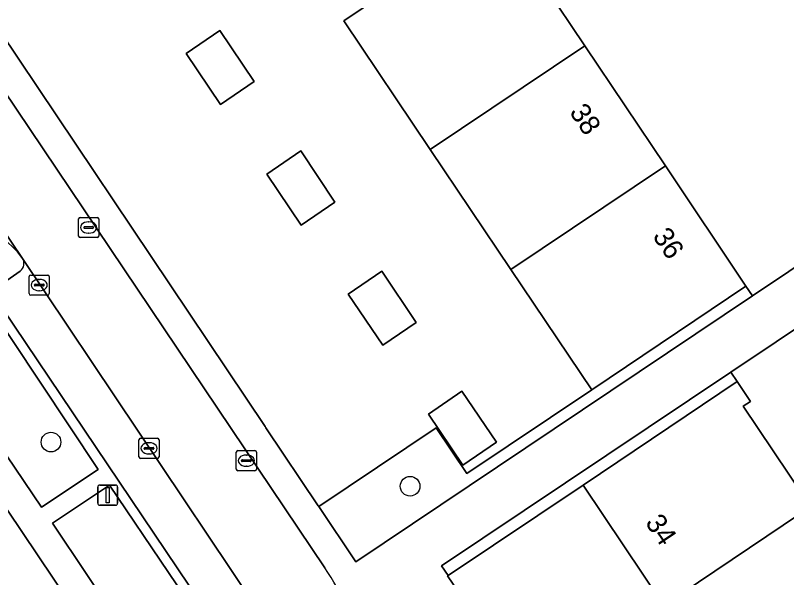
# Model space of a CAD drawing. Extents: x 158793 to 159888, y 384317 to 385256.
# Drawn here: x 159132.82 to 159171.17, y 384834.32 to 384862.27 of the extents above; entities that cross this region are included whole.
import ezdxf

# ---------------------------------------------------------------- set-up
doc = ezdxf.new("R2010")
doc.units = 0
for name, color, linetype in [('IMGEO_Boom', 7, 'Continuous'), ('IMGEO_Erf', 7, 'Continuous'), ('IMGEO_Groenvoorziening', 7, 'Continuous'), ('IMGEO_Kolk', 7, 'Continuous'), ('IMGEO_Lichtmast', 7, 'Continuous'), ('IMGEO_Pand', 7, 'Continuous'), ('IMGEO_Pand_nummerreeks', 7, 'Continuous'), ('IMGEO_Parkeervlak_open', 7, 'Continuous'), ('IMGEO_Rijbaan_lokaal_open', 7, 'Continuous'), ('IMGEO_Voetpad_open', 7, 'Continuous')]:
    doc.layers.add(name, color=color, linetype=linetype)

msp = doc.modelspace()

# ---------------------------------------------------------------- linework, layer by layer
at = {"layer": 'IMGEO_Boom'}
for centre in [(159134.592, 384841.055), (159152.449, 384838.86)]:
    msp.add_circle(centre, 0.489, dxfattribs=at)
at = {"layer": 'IMGEO_Erf'}
for points in [[(159129.189, 384865.748), (159145.236, 384841.838), (159145.281, 384841.77), (159147.886, 384837.889), (159147.91, 384837.853), (159153.744, 384841.768), (159155.277, 384839.485), (159161.48, 384843.659), (159157.462, 384849.64), (159153.451, 384855.61), (159149.155, 384862.006), (159151.132, 384863.344), (159147.414, 384868.879), (159143.399, 384874.856), (159138.645, 384881.934), (159140.628, 384883.267), (159137.261, 384888.273), (159133.15, 384894.387), (159129.299, 384900.113)], [(159178.672, 384807.366), (159174.655, 384813.355), (159170.638, 384819.344), (159173.118, 384820.976), (159169.097, 384826.953), (159165.075, 384832.93), (159161.054, 384838.907), (159154.343, 384834.428), (159154.314, 384834.409), (159155.612, 384832.486), (159157.414, 384829.817), (159158.347, 384828.435), (159166.834, 384815.86), (159164.988, 384814.597), (159177.008, 384796.687)]]:
    msp.add_lwpolyline(points, dxfattribs=at)
for points in [[(159142.985, 384861.523), (159144.7, 384858.986), (159143.015, 384857.836), (159141.307, 384860.374)], [(159148.707, 384852.981), (159147.034, 384851.839), (159145.325, 384854.381), (159147.013, 384855.54)], [(159151.039, 384849.551), (159152.759, 384847.01), (159151.088, 384845.867), (159149.37, 384848.405)], [(159155.029, 384843.585), (159156.752, 384841.043), (159155.08, 384839.91), (159153.361, 384842.448)]]:
    msp.add_lwpolyline(points, close=True, dxfattribs=at)
at = {"layer": 'IMGEO_Groenvoorziening'}
for points in [[(159157.136, 384866.739), (159161.141, 384860.764), (159165.145, 384854.79), (159169.15, 384848.815), (159169.48, 384848.323), (159178.617, 384854.449), (159173.187, 384865.839)], [(159179.731, 384852.112), (159168.401, 384844.531), (159168.717, 384844.067), (159169.38, 384843.079), (159169.012, 384842.838), (159172.028, 384838.344)], [(159127.59, 384851.332), (159126.404, 384850.498), (159125.828, 384850.069), (159134.112, 384837.817), (159136.939, 384839.685), (159131.178, 384848.335), (159131.464, 384848.516), (159131.607, 384848.549)], [(159131.607, 384848.549), (159133.059, 384849.561)]]:
    msp.add_lwpolyline(points, dxfattribs=at)
for points in [[(159169.48, 384848.323), (159169.15, 384848.815), (159161.48, 384843.659), (159155.277, 384839.485), (159153.744, 384841.768), (159147.91, 384837.853), (159149.746, 384835.092)], [(159161.054, 384838.907), (159168.717, 384844.067), (159168.401, 384844.531), (159154.011, 384834.902), (159154.343, 384834.428)], [(159137.509, 384838.918), (159134.663, 384837.03), (159139.797, 384829.364), (159140.593, 384828.294), (159143.37, 384830.219)]]:
    msp.add_lwpolyline(points, close=True, dxfattribs=at)
for centre, radius, start, end in [((159129.775, 384847.773), 4.176, 35.4147, 121.5438), ((159132.773, 384849.942), 0.476, 306.8491, 31.824)]:
    msp.add_arc(centre, radius, start, end, dxfattribs=at)
at = {"layer": 'IMGEO_Kolk'}
for p, q in [((159135.963, 384851.301), (159135.963, 384852.153)), ((159136.038, 384852.227), (159136.89, 384852.227)), ((159136.964, 384852.153), (159136.964, 384851.301)), ((159136.222, 384851.721), (159136.222, 384851.733)), ((159136.265, 384851.77), (159136.663, 384851.77)), ((159136.451, 384852.007), (159136.476, 384852.007)), ((159136.706, 384851.733), (159136.706, 384851.721)), ((159136.66, 384851.684), (159136.262, 384851.684)), ((159136.474, 384851.447), (159136.449, 384851.447)), ((159136.89, 384851.227), (159136.038, 384851.227)), ((159133.506, 384848.437), (159133.506, 384849.289)), ((159133.581, 384849.363), (159134.433, 384849.363)), ((159133.994, 384849.143), (159134.019, 384849.143)), ((159134.507, 384849.289), (159134.507, 384848.437)), ((159133.765, 384848.857), (159133.765, 384848.869)), ((159134.203, 384848.82), (159133.805, 384848.82)), ((159133.808, 384848.906), (159134.206, 384848.906)), ((159134.249, 384848.869), (159134.249, 384848.857)), ((159134.433, 384848.363), (159133.581, 384848.363)), ((159134.017, 384848.583), (159133.992, 384848.583)), ((159138.967, 384840.317), (159138.967, 384841.169)), ((159139.042, 384841.243), (159139.894, 384841.243)), ((159139.455, 384841.023), (159139.48, 384841.023)), ((159139.968, 384841.169), (159139.968, 384840.317)), ((159139.226, 384840.737), (159139.226, 384840.749)), ((159139.664, 384840.7), (159139.266, 384840.7)), ((159139.269, 384840.786), (159139.667, 384840.786)), ((159139.71, 384840.749), (159139.71, 384840.737)), ((159143.883, 384840.631), (159144.735, 384840.631)), ((159139.894, 384840.243), (159139.042, 384840.243)), ((159139.478, 384840.463), (159139.453, 384840.463)), ((159143.808, 384839.705), (159143.808, 384840.557)), ((159144.296, 384840.411), (159144.321, 384840.411)), ((159144.809, 384840.557), (159144.809, 384839.705)), ((159144.067, 384840.125), (159144.067, 384840.137)), ((159144.505, 384840.088), (159144.107, 384840.088)), ((159144.11, 384840.174), (159144.508, 384840.174)), ((159144.319, 384839.851), (159144.294, 384839.851)), ((159144.551, 384840.137), (159144.551, 384840.125)), ((159144.735, 384839.631), (159143.883, 384839.631))]:
    msp.add_line(p, q, dxfattribs=at)
for points in [[(159135.963, 384851.301), (159135.963, 384852.153)], [(159136.038, 384852.227), (159136.89, 384852.227)], [(159136.964, 384852.153), (159136.964, 384851.301)], [(159136.89, 384851.227), (159136.038, 384851.227)], [(159133.506, 384848.437), (159133.506, 384849.289)], [(159133.581, 384849.363), (159134.433, 384849.363)], [(159134.507, 384849.289), (159134.507, 384848.437)], [(159134.433, 384848.363), (159133.581, 384848.363)], [(159138.967, 384840.317), (159138.967, 384841.169)], [(159139.042, 384841.243), (159139.894, 384841.243)], [(159139.968, 384841.169), (159139.968, 384840.317)], [(159143.883, 384840.631), (159144.735, 384840.631)], [(159139.894, 384840.243), (159139.042, 384840.243)], [(159143.808, 384839.705), (159143.808, 384840.557)], [(159144.809, 384840.557), (159144.809, 384839.705)], [(159144.735, 384839.631), (159143.883, 384839.631)]]:
    msp.add_lwpolyline(points, dxfattribs=at)
for centre, radius, start, end in [((159136.04, 384852.151), 0.0765, 91.552, 178.448), ((159136.04, 384852.151), 0.0765, 91.552, 178.448), ((159136.888, 384852.151), 0.0765, 1.552, 88.448), ((159136.888, 384852.151), 0.0765, 1.552, 88.448), ((159136.262, 384851.73), 0.0403, 85.8775, 175.7526), ((159136.259, 384851.72), 0.0366, 178.938, 274.7102), ((159136.663, 384851.727), 0.043, 264.8664, 352.4533), ((159136.667, 384851.732), 0.0386, 1.7309, 96.639), ((159136.04, 384851.303), 0.0765, 181.552, 268.448), ((159136.04, 384851.303), 0.0765, 181.552, 268.448), ((159136.888, 384851.303), 0.0765, 271.552, 358.448), ((159136.888, 384851.303), 0.0765, 271.552, 358.448), ((159133.583, 384849.287), 0.0765, 91.552, 178.448), ((159133.583, 384849.287), 0.0765, 91.552, 178.448), ((159134.431, 384849.287), 0.0765, 1.552, 88.448), ((159134.431, 384849.287), 0.0765, 1.552, 88.448), ((159133.805, 384848.866), 0.0403, 85.8775, 175.7526), ((159133.802, 384848.856), 0.0366, 178.938, 274.7102), ((159134.206, 384848.863), 0.043, 264.8664, 352.4533), ((159134.21, 384848.868), 0.0386, 1.7309, 96.639), ((159133.583, 384848.439), 0.0765, 181.552, 268.448), ((159133.583, 384848.439), 0.0765, 181.552, 268.448), ((159134.431, 384848.439), 0.0765, 271.552, 358.448), ((159134.431, 384848.439), 0.0765, 271.552, 358.448), ((159139.044, 384841.167), 0.0765, 91.552, 178.448), ((159139.044, 384841.167), 0.0765, 91.552, 178.448), ((159139.892, 384841.167), 0.0765, 1.552, 88.448), ((159139.892, 384841.167), 0.0765, 1.552, 88.448), ((159139.266, 384840.746), 0.0403, 85.8775, 175.7526), ((159139.263, 384840.736), 0.0366, 178.938, 274.7102), ((159139.667, 384840.743), 0.043, 264.8664, 352.4533), ((159139.671, 384840.748), 0.0386, 1.7309, 96.639), ((159143.885, 384840.555), 0.0765, 91.552, 178.448), ((159143.885, 384840.555), 0.0765, 91.552, 178.448), ((159144.733, 384840.555), 0.0765, 1.552, 88.448), ((159144.733, 384840.555), 0.0765, 1.552, 88.448), ((159139.044, 384840.319), 0.0765, 181.552, 268.448), ((159139.044, 384840.319), 0.0765, 181.552, 268.448), ((159139.892, 384840.319), 0.0765, 271.552, 358.448), ((159139.892, 384840.319), 0.0765, 271.552, 358.448), ((159144.107, 384840.134), 0.0403, 85.8775, 175.7526), ((159144.104, 384840.124), 0.0366, 178.938, 274.7102), ((159144.508, 384840.131), 0.043, 264.8664, 352.4533), ((159144.512, 384840.136), 0.0386, 1.7309, 96.639), ((159143.885, 384839.707), 0.0765, 181.552, 268.448), ((159143.885, 384839.707), 0.0765, 181.552, 268.448), ((159144.733, 384839.707), 0.0765, 271.552, 358.448), ((159144.733, 384839.707), 0.0765, 271.552, 358.448)]:
    msp.add_arc(centre, radius, start, end, dxfattribs=at)
for centre, major_axis, ratio, start_param, end_param in [((159136.45, 384851.727), (-0.387, 0.002), 0.722429, 4.712389, 7.853982), ((159136.475, 384851.727), (-0.39, 0.002), 0.717154, 1.570796, 4.712389), ((159133.993, 384848.863), (-0.387, 0.002), 0.722429, 4.712389, 7.853982), ((159134.018, 384848.863), (-0.39, 0.002), 0.717154, 1.570796, 4.712389), ((159139.454, 384840.743), (-0.387, 0.002), 0.722429, 4.712389, 7.853982), ((159139.479, 384840.743), (-0.39, 0.002), 0.717154, 1.570796, 4.712389), ((159144.295, 384840.131), (-0.387, 0.002), 0.722429, 4.712389, 7.853982), ((159144.32, 384840.131), (-0.39, 0.002), 0.717154, 1.570796, 4.712389)]:
    msp.add_ellipse(centre, major_axis=major_axis, ratio=ratio, start_param=start_param, end_param=end_param, dxfattribs=at)
at = {"layer": 'IMGEO_Lichtmast'}
for p, q in [((159136.916, 384838.016), (159136.916, 384838.816)), ((159136.916, 384838.816), (159136.916, 384838.016)), ((159137.016, 384838.916), (159137.806, 384838.916)), ((159137.806, 384838.916), (159137.016, 384838.916)), ((159137.906, 384838.816), (159137.906, 384838.016)), ((159137.906, 384838.016), (159137.906, 384838.816)), ((159137.806, 384837.916), (159137.016, 384837.916)), ((159137.016, 384837.916), (159137.806, 384837.916))]:
    msp.add_line(p, q, dxfattribs=at)
msp.add_lwpolyline([(159137.336, 384838.791), (159137.486, 384838.791), (159137.486, 384838.041), (159137.336, 384838.041), (159137.336, 384838.791)], dxfattribs=at)
for centre, start, end in [((159137.016, 384838.816), 90, 180), ((159137.016, 384838.816), 90, 180), ((159137.806, 384838.816), 0, 90), ((159137.806, 384838.816), 360, 90), ((159137.016, 384838.016), 180, 270), ((159137.016, 384838.016), 180, 270), ((159137.806, 384838.016), 270, 0), ((159137.806, 384838.016), 270, 0)]:
    msp.add_arc(centre, 0.1, start, end, dxfattribs=at)
at = {"layer": 'IMGEO_Pand'}
for points in [[(159157.136, 384866.739), (159151.409, 384862.932), (159151.132, 384863.344), (159149.155, 384862.006), (159153.451, 384855.61), (159161.141, 384860.764)], [(159143.015, 384857.836), (159144.7, 384858.986), (159142.985, 384861.523), (159141.307, 384860.374)], [(159161.141, 384860.764), (159153.451, 384855.61), (159157.462, 384849.64), (159165.145, 384854.79)], [(159148.707, 384852.981), (159147.013, 384855.54), (159145.325, 384854.381), (159147.034, 384851.839)], [(159165.145, 384854.79), (159157.462, 384849.64), (159161.48, 384843.659), (159169.15, 384848.815)], [(159151.088, 384845.867), (159152.759, 384847.01), (159151.039, 384849.551), (159149.37, 384848.405)], [(159172.733, 384838.082), (159172.392, 384838.59), (159172.028, 384838.344), (159169.012, 384842.838), (159169.38, 384843.079), (159168.717, 384844.067), (159161.054, 384838.907), (159165.075, 384832.93)], [(159153.361, 384842.448), (159155.08, 384839.91), (159156.752, 384841.043), (159155.029, 384843.585)], [(159176.407, 384832.607), (159176.042, 384832.362), (159173.019, 384836.867), (159173.394, 384837.097), (159172.733, 384838.082), (159165.075, 384832.93), (159169.097, 384826.953), (159176.747, 384832.1)], [(159132.426, 384837.666), (159127.542, 384834.383), (159128.207, 384833.381), (159133.576, 384825.406), (159134.485, 384826.016), (159134.121, 384826.552), (159135.262, 384827.327), (159135.51, 384826.964), (159137.416, 384828.259), (159137.546, 384828.069), (159138.469, 384828.688)]]:
    msp.add_lwpolyline(points, close=True, dxfattribs=at)
at = {"layer": 'IMGEO_Parkeervlak_open'}
for points in [[(159144.677, 384833.004), (159133.178, 384850.193)], [(159133.059, 384849.561), (159131.607, 384848.549), (159143.771, 384830.497), (159145.43, 384831.589)]]:
    msp.add_lwpolyline(points, dxfattribs=at)
msp.add_arc((159132.773, 384849.942), 0.476, 306.8491, 31.824, dxfattribs=at)
at = {"layer": 'IMGEO_Rijbaan_lokaal_open'}
for points in [[(159148.203, 384834.797), (159118.86, 384878.459), (159111.767, 384888.566), (159104.966, 384899.16), (159103.806, 384898.409), (159096.869, 384908.495), (159087.727, 384922.129), (159083.943, 384919.604), (159075.859, 384931.636), (159073.188, 384929.845), (159064.372, 384942.983), (159064.012, 384943.519), (159063.774, 384943.363), (159060.822, 384941.424), (159063.201, 384937.96), (159070.121, 384927.644), (159074.586, 384920.972)], [(159112.267, 384881.254), (159112.297, 384881.21), (159125.401, 384861.714), (159133.178, 384850.193), (159144.677, 384833.004)], [(159133.178, 384850.193), (159125.401, 384861.714)]]:
    msp.add_lwpolyline(points, dxfattribs=at)
for centre, radius, start, end in [((159129.775, 384847.773), 4.176, 35.4147, 121.5438), ((159140.067, 384829.043), 9.965, 9.2261, 35.2676)]:
    msp.add_arc(centre, radius, start, end, dxfattribs=at)
at = {"layer": 'IMGEO_Voetpad_open'}
for points in [[(159129.189, 384865.748), (159122.184, 384876.186), (159122.968, 384876.772), (159106.267, 384901.604), (159104.197, 384900.201), (159088.084, 384924.2), (159084.288, 384921.691), (159076.292, 384933.589), (159073.613, 384931.81), (159065.871, 384943.305), (159065.557, 384943.772), (159064.372, 384942.983), (159073.188, 384929.845), (159075.859, 384931.636), (159083.943, 384919.604), (159087.727, 384922.129), (159096.869, 384908.495), (159103.806, 384898.409), (159104.966, 384899.16), (159111.767, 384888.566), (159118.86, 384878.459), (159148.203, 384834.797)], [(159151.595, 384829.55), (159151.512, 384829.903), (159155.612, 384832.486), (159154.314, 384834.409), (159154.343, 384834.428), (159154.011, 384834.902), (159168.401, 384844.531), (159179.731, 384852.112), (159183.747, 384854.799), (159185.084, 384855.667), (159183.957, 384858.019), (159182.672, 384857.168), (159178.617, 384854.449), (159169.48, 384848.323), (159149.746, 384835.092), (159147.91, 384837.853), (159147.886, 384837.889), (159145.281, 384841.77), (159145.236, 384841.838), (159129.189, 384865.748)], [(159131.607, 384848.549), (159131.464, 384848.516), (159131.178, 384848.335), (159136.939, 384839.685), (159134.112, 384837.817), (159125.828, 384850.069), (159124.629, 384849.25), (159124.803, 384848.991), (159128.177, 384843.979), (159128.473, 384843.539), (159132.426, 384837.666), (159138.469, 384828.688), (159140.397, 384825.767), (159142.395, 384822.861), (159143.651, 384823.723), (159141.656, 384826.635), (159145.384, 384829.198)], [(159146.047, 384828.889), (159145.748, 384830.352), (159145.43, 384831.589), (159143.771, 384830.497), (159131.607, 384848.549)]]:
    msp.add_lwpolyline(points, dxfattribs=at)
msp.add_lwpolyline([(159137.509, 384838.918), (159143.37, 384830.219), (159140.593, 384828.294), (159139.797, 384829.364), (159134.663, 384837.03)], close=True, dxfattribs=at)
msp.add_arc((159140.067, 384829.043), 9.965, 9.2261, 35.2676, dxfattribs=at)

# ---------------------------------------------------------------- texts
at = {"layer": 'IMGEO_Pand_nummerreeks'}
for s, rotation, p in [('38', 303.8329, (159160.344, 384857.464)), ('36', 303.8329, (159164.479, 384851.294)), ('34', 303.9304, (159164.112, 384837.048))]:
    msp.add_text(s, height=1, rotation=rotation, dxfattribs=at).set_placement(p)

doc.saveas('drawing.dxf')
